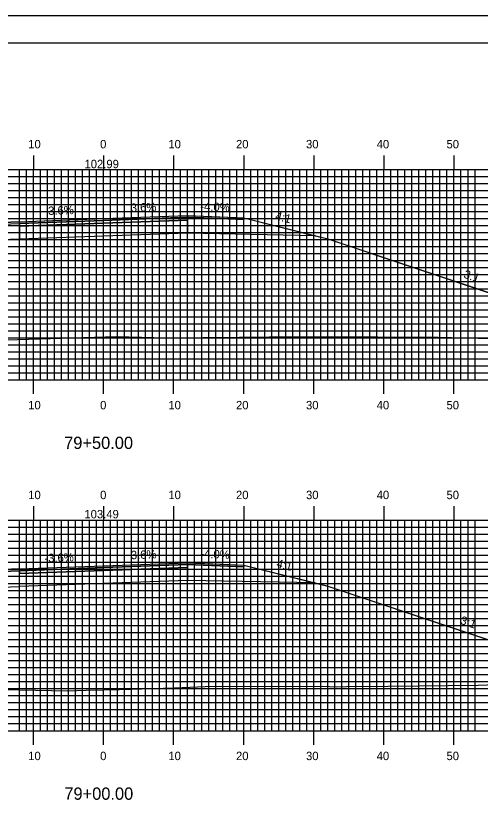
# Model space of a CAD drawing. Extents: x 1762184 to 1762528, y 442591 to 442811.
# Drawn here: x 1762337.8 to 1762404, y 442697.1 to 442810.5 of the extents above; entities that cross this region are included whole.
import ezdxf

# ---------------------------------------------------------------- set-up
doc = ezdxf.new("R2010")
doc.units = 0
for name, color, linetype in [('ANNOTATION', 7, 'Continuous'), ('BORDER', 7, 'Continuous'), ('D_Roadway_Centerline', 7, 'Continuous'), ('D_Roadway_Centerline_Text', 7, 'Continuous'), ('D_Roadway_Edge_Shoulder', 7, 'Continuous'), ('D_Roadway_Edge_TW', 7, 'Continuous'), ('D_Roadway_Pavement', 7, 'Continuous'), ('D_Roadway_SlopeLines', 7, 'Continuous'), ('D_Roadway_SubGrade', 7, 'Continuous'), ('H_V ANNOTATION', 7, 'Continuous'), ('MAJOR', 7, 'Continuous'), ('MINOR', 7, 'Continuous'), ('PLOT BOUNDARY', 7, 'Continuous'), ('S_Roadway_Centerline', 7, 'Continuous')]:
    doc.layers.add(name, color=color, linetype=linetype)

msp = doc.modelspace()

# ---------------------------------------------------------------- linework, layer by layer
at = {"layer": 'BORDER'}
msp.add_lwpolyline([(1762200.67, 442596.67), (1762520.67, 442596.67), (1762520.67, 442806.67), (1762200.67, 442806.67)], close=True, dxfattribs=at)
at = {"layer": 'D_Roadway_Centerline'}
for points in [[(1762326.92, 442780.77), (1762338.26, 442781.22), (1762338.27, 442781.22), (1762346.49, 442781.52), (1762350.26, 442781.66), (1762350.27, 442781.66), (1762350.27, 442781.66), (1762362.27, 442782.09), (1762362.27, 442782.09), (1762370.27, 442781.77), (1762380.13, 442779.3), (1762380.44, 442779.22), (1762380.51, 442779.21), (1762382.27, 442778.77), (1762382.28, 442778.76), (1762418.67, 442766.63)], [(1762332.89, 442731.51), (1762338.26, 442731.72), (1762338.27, 442731.72), (1762338.27, 442731.72), (1762346.33, 442732.01), (1762350.26, 442732.15), (1762350.27, 442732.16), (1762350.28, 442732.16), (1762362.27, 442732.59), (1762367.13, 442732.39), (1762370.27, 442732.27), (1762370.27, 442732.27), (1762380.44, 442729.72), (1762381.02, 442729.58), (1762382.27, 442729.27), (1762420.68, 442716.46)]]:
    msp.add_lwpolyline(points, dxfattribs=at)
at = {"layer": 'D_Roadway_Edge_Shoulder'}
for points in [[(1762362.27, 442782.09), (1762370.27, 442781.77), (1762370.27, 442781.52), (1762362.27, 442781.84)], [(1762338.27, 442781.22), (1762324.66, 442780.68), (1762324.66, 442780.43), (1762338.27, 442780.97)], [(1762362.27, 442732.59), (1762370.27, 442732.27), (1762370.27, 442732.02), (1762362.27, 442732.34)], [(1762338.27, 442731.72), (1762330.27, 442731.4), (1762330.27, 442731.4), (1762327.27, 442731.28), (1762327.27, 442731.03), (1762338.27, 442731.47)]]:
    msp.add_lwpolyline(points, close=True, dxfattribs=at)
at = {"layer": 'D_Roadway_Edge_TW'}
for points in [[(1762338.27, 442780.97), (1762338.27, 442781.22), (1762350.27, 442781.66), (1762362.27, 442782.09), (1762362.27, 442781.84), (1762350.27, 442781.41)], [(1762362.27, 442782.09), (1762362.27, 442782.09), (1762362.27, 442781.84), (1762362.27, 442781.84)], [(1762338.27, 442731.47), (1762338.27, 442731.72), (1762350.27, 442732.16), (1762362.27, 442732.59), (1762362.27, 442732.34), (1762350.27, 442731.91)]]:
    msp.add_lwpolyline(points, close=True, dxfattribs=at)
at = {"layer": 'D_Roadway_Pavement'}
for points in [[(1762338.27, 442780.56), (1762338.27, 442780.97), (1762350.27, 442781.41), (1762362.27, 442781.84), (1762362.27, 442781.42), (1762350.27, 442780.99)], [(1762362.27, 442781.84), (1762362.27, 442781.84), (1762362.27, 442781.42), (1762362.27, 442781.42)], [(1762338.27, 442731.06), (1762338.27, 442731.47), (1762350.27, 442731.91), (1762362.27, 442732.34), (1762362.27, 442731.92), (1762350.27, 442731.49)]]:
    msp.add_lwpolyline(points, close=True, dxfattribs=at)
for points in [[(1762362.27, 442781.84), (1762362.27, 442781.42)], [(1762362.27, 442781.84), (1762362.27, 442781.42)], [(1762362.27, 442781.84), (1762362.27, 442781.42)], [(1762338.27, 442731.47), (1762338.27, 442731.06)], [(1762362.27, 442732.34), (1762362.27, 442731.92)]]:
    msp.add_lwpolyline(points, dxfattribs=at)
at = {"layer": 'D_Roadway_SlopeLines'}
for points in [[(1762370.27, 442781.77), (1762382.27, 442778.77), (1762421.63, 442765.65)], [(1762370.27, 442732.27), (1762382.27, 442729.27), (1762421.95, 442716.04)]]:
    msp.add_lwpolyline(points, dxfattribs=at)
at = {"layer": 'D_Roadway_SubGrade'}
for points in [[(1762338.27, 442778.72), (1762338.27, 442780.56), (1762350.27, 442780.99), (1762362.27, 442781.42), (1762362.27, 442779.59), (1762350.27, 442779.16)], [(1762362.27, 442781.42), (1762362.27, 442781.84), (1762370.27, 442781.52), (1762370.27, 442781.77), (1762380.44, 442779.22), (1762362.27, 442779.59)], [(1762362.27, 442781.42), (1762362.27, 442781.42), (1762362.27, 442779.59), (1762362.27, 442779.59)], [(1762324.66, 442780.43), (1762338.27, 442780.97), (1762338.27, 442780.56), (1762338.27, 442778.72), (1762315.47, 442777.9), (1762324.66, 442780.68)], [(1762338.27, 442731.06), (1762338.27, 442731.47), (1762327.27, 442731.03), (1762327.27, 442731.28), (1762319.01, 442728.53), (1762338.27, 442729.22)], [(1762338.27, 442729.22), (1762338.27, 442731.47), (1762338.27, 442731.06), (1762350.27, 442731.49), (1762362.27, 442731.92), (1762362.27, 442732.34), (1762362.27, 442730.09), (1762350.27, 442729.66)], [(1762362.27, 442731.92), (1762362.27, 442732.34), (1762370.27, 442732.02), (1762370.27, 442732.27), (1762380.44, 442729.72), (1762362.27, 442730.09)]]:
    msp.add_lwpolyline(points, close=True, dxfattribs=at)
at = {"layer": 'MAJOR'}
for p, q in [((1762340.27, 442790.67), (1762340.27, 442788.67)), ((1762350.27, 442790.67), (1762350.27, 442788.67)), ((1762360.27, 442790.67), (1762360.27, 442788.67)), ((1762370.27, 442790.67), (1762370.27, 442788.67)), ((1762380.27, 442790.67), (1762380.27, 442788.67)), ((1762390.27, 442790.67), (1762390.27, 442788.67)), ((1762400.27, 442790.67), (1762400.27, 442788.67)), ((1762210.27, 442788.67), (1762490.27, 442788.67)), ((1762210.27, 442788.67), (1762490.27, 442788.67)), ((1762340.27, 442758.67), (1762340.27, 442788.67)), ((1762350.27, 442758.67), (1762350.27, 442788.67)), ((1762360.27, 442758.67), (1762360.27, 442788.67)), ((1762370.27, 442758.67), (1762370.27, 442788.67)), ((1762380.27, 442758.67), (1762380.27, 442788.67)), ((1762390.27, 442758.67), (1762390.27, 442788.67)), ((1762400.27, 442758.67), (1762400.27, 442788.67)), ((1762210.27, 442783.67), (1762490.27, 442783.67)), ((1762210.27, 442778.67), (1762490.27, 442778.67)), ((1762210.27, 442773.67), (1762490.27, 442773.67)), ((1762210.27, 442768.67), (1762490.27, 442768.67)), ((1762210.27, 442763.67), (1762490.27, 442763.67)), ((1762210.27, 442758.67), (1762490.27, 442758.67)), ((1762210.27, 442758.67), (1762490.27, 442758.67)), ((1762340.27, 442756.66), (1762340.27, 442758.67)), ((1762350.27, 442756.66), (1762350.27, 442758.67)), ((1762360.27, 442756.66), (1762360.27, 442758.67)), ((1762370.27, 442756.66), (1762370.27, 442758.67)), ((1762380.27, 442756.66), (1762380.27, 442758.67)), ((1762390.27, 442756.66), (1762390.27, 442758.67)), ((1762400.27, 442756.66), (1762400.27, 442758.67)), ((1762340.27, 442740.67), (1762340.27, 442738.67)), ((1762350.27, 442740.67), (1762350.27, 442738.67)), ((1762360.27, 442740.67), (1762360.27, 442738.67)), ((1762370.27, 442740.67), (1762370.27, 442738.67)), ((1762380.27, 442740.67), (1762380.27, 442738.67)), ((1762390.27, 442740.67), (1762390.27, 442738.67)), ((1762400.27, 442740.67), (1762400.27, 442738.67)), ((1762210.27, 442738.67), (1762490.27, 442738.67)), ((1762210.27, 442738.67), (1762490.27, 442738.67)), ((1762340.27, 442708.67), (1762340.27, 442738.67)), ((1762350.27, 442708.67), (1762350.27, 442738.67)), ((1762360.27, 442708.67), (1762360.27, 442738.67)), ((1762370.27, 442708.67), (1762370.27, 442738.67)), ((1762380.27, 442708.67), (1762380.27, 442738.67)), ((1762390.27, 442708.67), (1762390.27, 442738.67)), ((1762400.27, 442708.67), (1762400.27, 442738.67)), ((1762210.27, 442733.67), (1762490.27, 442733.67)), ((1762210.27, 442728.67), (1762490.27, 442728.67)), ((1762210.27, 442723.67), (1762490.27, 442723.67)), ((1762210.27, 442718.67), (1762490.27, 442718.67)), ((1762210.27, 442713.67), (1762490.27, 442713.67)), ((1762210.27, 442708.67), (1762490.27, 442708.67)), ((1762210.27, 442708.67), (1762490.27, 442708.67)), ((1762340.27, 442706.66), (1762340.27, 442708.67)), ((1762350.27, 442706.66), (1762350.27, 442708.67)), ((1762360.27, 442706.66), (1762360.27, 442708.67)), ((1762370.27, 442706.66), (1762370.27, 442708.67)), ((1762380.27, 442706.66), (1762380.27, 442708.67)), ((1762390.27, 442706.66), (1762390.27, 442708.67)), ((1762400.27, 442706.66), (1762400.27, 442708.67))]:
    msp.add_line(p, q, dxfattribs=at)
at = {"layer": 'MINOR'}
for p, q in [((1762338.27, 442758.67), (1762338.27, 442788.67)), ((1762339.27, 442758.67), (1762339.27, 442788.67)), ((1762341.27, 442758.67), (1762341.27, 442788.67)), ((1762342.27, 442758.67), (1762342.27, 442788.67)), ((1762343.27, 442758.67), (1762343.27, 442788.67)), ((1762344.27, 442758.67), (1762344.27, 442788.67)), ((1762345.27, 442758.67), (1762345.27, 442788.67)), ((1762346.27, 442758.67), (1762346.27, 442788.67)), ((1762347.27, 442758.67), (1762347.27, 442788.67)), ((1762348.27, 442758.67), (1762348.27, 442788.67)), ((1762349.27, 442758.67), (1762349.27, 442788.67)), ((1762351.27, 442758.67), (1762351.27, 442788.67)), ((1762352.27, 442758.67), (1762352.27, 442788.67)), ((1762353.27, 442758.67), (1762353.27, 442788.67)), ((1762354.27, 442758.67), (1762354.27, 442788.67)), ((1762355.27, 442758.67), (1762355.27, 442788.67)), ((1762356.27, 442758.67), (1762356.27, 442788.67)), ((1762357.27, 442758.67), (1762357.27, 442788.67)), ((1762358.27, 442758.67), (1762358.27, 442788.67)), ((1762359.27, 442758.67), (1762359.27, 442788.67)), ((1762361.27, 442758.67), (1762361.27, 442788.67)), ((1762362.27, 442758.67), (1762362.27, 442788.67)), ((1762363.27, 442758.67), (1762363.27, 442788.67)), ((1762364.27, 442758.67), (1762364.27, 442788.67)), ((1762365.27, 442758.67), (1762365.27, 442788.67)), ((1762366.27, 442758.67), (1762366.27, 442788.67)), ((1762367.27, 442758.67), (1762367.27, 442788.67)), ((1762368.27, 442758.67), (1762368.27, 442788.67)), ((1762369.27, 442758.67), (1762369.27, 442788.67)), ((1762371.27, 442758.67), (1762371.27, 442788.67)), ((1762372.27, 442758.67), (1762372.27, 442788.67)), ((1762373.27, 442758.67), (1762373.27, 442788.67)), ((1762374.27, 442758.67), (1762374.27, 442788.67)), ((1762375.27, 442758.67), (1762375.27, 442788.67)), ((1762376.27, 442758.67), (1762376.27, 442788.67)), ((1762377.27, 442758.67), (1762377.27, 442788.67)), ((1762378.27, 442758.67), (1762378.27, 442788.67)), ((1762379.27, 442758.67), (1762379.27, 442788.67)), ((1762381.27, 442758.67), (1762381.27, 442788.67)), ((1762382.27, 442758.67), (1762382.27, 442788.67)), ((1762383.27, 442758.67), (1762383.27, 442788.67)), ((1762384.27, 442758.67), (1762384.27, 442788.67)), ((1762385.27, 442758.67), (1762385.27, 442788.67)), ((1762386.27, 442758.67), (1762386.27, 442788.67)), ((1762387.27, 442758.67), (1762387.27, 442788.67)), ((1762388.27, 442758.67), (1762388.27, 442788.67)), ((1762389.27, 442758.67), (1762389.27, 442788.67)), ((1762391.27, 442758.67), (1762391.27, 442788.67)), ((1762392.27, 442758.67), (1762392.27, 442788.67)), ((1762393.27, 442758.67), (1762393.27, 442788.67)), ((1762394.27, 442758.67), (1762394.27, 442788.67)), ((1762395.27, 442758.67), (1762395.27, 442788.67)), ((1762396.27, 442758.67), (1762396.27, 442788.67)), ((1762397.27, 442758.67), (1762397.27, 442788.67)), ((1762398.27, 442758.67), (1762398.27, 442788.67)), ((1762399.27, 442758.67), (1762399.27, 442788.67)), ((1762401.27, 442758.67), (1762401.27, 442788.67)), ((1762402.27, 442758.67), (1762402.27, 442788.67)), ((1762403.27, 442758.67), (1762403.27, 442788.67)), ((1762210.27, 442787.67), (1762490.27, 442787.67)), ((1762210.27, 442786.67), (1762490.27, 442786.67)), ((1762210.27, 442785.67), (1762490.27, 442785.67)), ((1762210.27, 442784.67), (1762490.27, 442784.67)), ((1762210.27, 442782.67), (1762490.27, 442782.67)), ((1762210.27, 442781.67), (1762490.27, 442781.67)), ((1762210.27, 442780.67), (1762490.27, 442780.67)), ((1762210.27, 442779.67), (1762490.27, 442779.67)), ((1762210.27, 442777.67), (1762490.27, 442777.67)), ((1762210.27, 442776.67), (1762490.27, 442776.67)), ((1762210.27, 442775.67), (1762490.27, 442775.67)), ((1762210.27, 442774.67), (1762490.27, 442774.67)), ((1762210.27, 442772.67), (1762490.27, 442772.67)), ((1762210.27, 442771.67), (1762490.27, 442771.67)), ((1762210.27, 442770.67), (1762490.27, 442770.67)), ((1762210.27, 442769.67), (1762490.27, 442769.67)), ((1762210.27, 442767.67), (1762490.27, 442767.67)), ((1762210.27, 442766.67), (1762490.27, 442766.67)), ((1762210.27, 442765.67), (1762490.27, 442765.67)), ((1762210.27, 442764.67), (1762490.27, 442764.67)), ((1762210.27, 442762.67), (1762490.27, 442762.67)), ((1762210.27, 442761.67), (1762490.27, 442761.67)), ((1762210.27, 442760.67), (1762490.27, 442760.67)), ((1762210.27, 442759.67), (1762490.27, 442759.67)), ((1762338.27, 442708.67), (1762338.27, 442738.67)), ((1762339.27, 442708.67), (1762339.27, 442738.67)), ((1762341.27, 442708.67), (1762341.27, 442738.67)), ((1762342.27, 442708.67), (1762342.27, 442738.67)), ((1762343.27, 442708.67), (1762343.27, 442738.67)), ((1762344.27, 442708.67), (1762344.27, 442738.67)), ((1762345.27, 442708.67), (1762345.27, 442738.67)), ((1762346.27, 442708.67), (1762346.27, 442738.67)), ((1762347.27, 442708.67), (1762347.27, 442738.67)), ((1762348.27, 442708.67), (1762348.27, 442738.67)), ((1762349.27, 442708.67), (1762349.27, 442738.67)), ((1762351.27, 442708.67), (1762351.27, 442738.67)), ((1762352.27, 442708.67), (1762352.27, 442738.67)), ((1762353.27, 442708.67), (1762353.27, 442738.67)), ((1762354.27, 442708.67), (1762354.27, 442738.67)), ((1762355.27, 442708.67), (1762355.27, 442738.67)), ((1762356.27, 442708.67), (1762356.27, 442738.67)), ((1762357.27, 442708.67), (1762357.27, 442738.67)), ((1762358.27, 442708.67), (1762358.27, 442738.67)), ((1762359.27, 442708.67), (1762359.27, 442738.67)), ((1762361.27, 442708.67), (1762361.27, 442738.67)), ((1762362.27, 442708.67), (1762362.27, 442738.67)), ((1762363.27, 442708.67), (1762363.27, 442738.67)), ((1762364.27, 442708.67), (1762364.27, 442738.67)), ((1762365.27, 442708.67), (1762365.27, 442738.67)), ((1762366.27, 442708.67), (1762366.27, 442738.67)), ((1762367.27, 442708.67), (1762367.27, 442738.67)), ((1762368.27, 442708.67), (1762368.27, 442738.67)), ((1762369.27, 442708.67), (1762369.27, 442738.67)), ((1762371.27, 442708.67), (1762371.27, 442738.67)), ((1762372.27, 442708.67), (1762372.27, 442738.67)), ((1762373.27, 442708.67), (1762373.27, 442738.67)), ((1762374.27, 442708.67), (1762374.27, 442738.67)), ((1762375.27, 442708.67), (1762375.27, 442738.67)), ((1762376.27, 442708.67), (1762376.27, 442738.67)), ((1762377.27, 442708.67), (1762377.27, 442738.67)), ((1762378.27, 442708.67), (1762378.27, 442738.67)), ((1762379.27, 442708.67), (1762379.27, 442738.67)), ((1762381.27, 442708.67), (1762381.27, 442738.67)), ((1762382.27, 442708.67), (1762382.27, 442738.67)), ((1762383.27, 442708.67), (1762383.27, 442738.67)), ((1762384.27, 442708.67), (1762384.27, 442738.67)), ((1762385.27, 442708.67), (1762385.27, 442738.67)), ((1762386.27, 442708.67), (1762386.27, 442738.67)), ((1762387.27, 442708.67), (1762387.27, 442738.67)), ((1762388.27, 442708.67), (1762388.27, 442738.67)), ((1762389.27, 442708.67), (1762389.27, 442738.67)), ((1762391.27, 442708.67), (1762391.27, 442738.67)), ((1762392.27, 442708.67), (1762392.27, 442738.67)), ((1762393.27, 442708.67), (1762393.27, 442738.67)), ((1762394.27, 442708.67), (1762394.27, 442738.67)), ((1762395.27, 442708.67), (1762395.27, 442738.67)), ((1762396.27, 442708.67), (1762396.27, 442738.67)), ((1762397.27, 442708.67), (1762397.27, 442738.67)), ((1762398.27, 442708.67), (1762398.27, 442738.67)), ((1762399.27, 442708.67), (1762399.27, 442738.67)), ((1762401.27, 442708.67), (1762401.27, 442738.67)), ((1762402.27, 442708.67), (1762402.27, 442738.67)), ((1762403.27, 442708.67), (1762403.27, 442738.67)), ((1762210.27, 442737.67), (1762490.27, 442737.67)), ((1762210.27, 442736.67), (1762490.27, 442736.67)), ((1762210.27, 442735.67), (1762490.27, 442735.67)), ((1762210.27, 442734.67), (1762490.27, 442734.67)), ((1762210.27, 442732.67), (1762490.27, 442732.67)), ((1762210.27, 442731.67), (1762490.27, 442731.67)), ((1762210.27, 442730.67), (1762490.27, 442730.67)), ((1762210.27, 442729.67), (1762490.27, 442729.67)), ((1762210.27, 442727.67), (1762490.27, 442727.67)), ((1762210.27, 442726.67), (1762490.27, 442726.67)), ((1762210.27, 442725.67), (1762490.27, 442725.67)), ((1762210.27, 442724.67), (1762490.27, 442724.67)), ((1762210.27, 442722.67), (1762490.27, 442722.67)), ((1762210.27, 442721.67), (1762490.27, 442721.67)), ((1762210.27, 442720.67), (1762490.27, 442720.67)), ((1762210.27, 442719.67), (1762490.27, 442719.67)), ((1762210.27, 442717.67), (1762490.27, 442717.67)), ((1762210.27, 442716.67), (1762490.27, 442716.67)), ((1762210.27, 442715.67), (1762490.27, 442715.67)), ((1762210.27, 442714.67), (1762490.27, 442714.67)), ((1762210.27, 442712.67), (1762490.27, 442712.67)), ((1762210.27, 442711.67), (1762490.27, 442711.67)), ((1762210.27, 442710.67), (1762490.27, 442710.67)), ((1762210.27, 442709.67), (1762490.27, 442709.67))]:
    msp.add_line(p, q, dxfattribs=at)
at = {"layer": 'PLOT BOUNDARY'}
msp.add_lwpolyline([(1762184.48, 442590.55), (1762524.48, 442590.55), (1762524.48, 442810.55), (1762184.48, 442810.55)], close=True, dxfattribs=at)
at = {"layer": 'S_Roadway_Centerline'}
for points in [[(1762210.27, 442764.43), (1762228.23, 442764.73), (1762233.82, 442764.78), (1762239.74, 442764.65), (1762248.97, 442764.72), (1762253.17, 442764.72), (1762263.54, 442764.73), (1762272.55, 442764.79), (1762280.38, 442764.77), (1762287.62, 442764.62), (1762292.89, 442764.49), (1762309.79, 442764.84), (1762312.42, 442764.95), (1762318.72, 442764.73), (1762332.24, 442764.31), (1762334.82, 442764.33), (1762352.11, 442764.85), (1762359.24, 442764.67), (1762369.65, 442764.78), (1762371.28, 442764.74), (1762373.9, 442764.79), (1762389.4, 442764.82), (1762398, 442764.77), (1762405.61, 442764.58)], [(1762267.38, 442714.83), (1762277.69, 442714.96), (1762285.47, 442714.55), (1762289.59, 442714.53), (1762294.88, 442714.46), (1762300.94, 442714.53), (1762304.82, 442714.61), (1762323.81, 442714.78), (1762325.32, 442714.74), (1762329.07, 442714.69), (1762345.13, 442714.37), (1762347.81, 442714.46), (1762352.54, 442714.56), (1762360.38, 442714.79), (1762364.78, 442714.97), (1762381.51, 442715), (1762383.49, 442714.91), (1762384.95, 442714.97), (1762390.9, 442714.99), (1762403.74, 442715.17), (1762411.4, 442715.43)]]:
    msp.add_lwpolyline(points, dxfattribs=at)

# ---------------------------------------------------------------- texts
at = {"layer": 'ANNOTATION'}
for s, rotation, p in [('3.6%', 2.0618, (1762354.17, 442782.6)), ('-4.0%', 357.7094, (1762364.06, 442782.82)), ('-3.6%', 2.0617, (1762341.85, 442782.15)), ('4:1', 345.9607, (1762374.7, 442781.52)), ('3:1', 341.5644, (1762401.56, 442773.25)), ('-3.6%', 2.0617, (1762341.85, 442732.65)), ('3.6%', 2.0618, (1762354.18, 442733.1)), ('-4.0%', 357.7093, (1762364.06, 442733.32)), ('4:1', 345.962, (1762374.86, 442731.98)), ('3:1', 341.5642, (1762401.08, 442723.91))]:
    msp.add_text(s, height=1.2, rotation=rotation, dxfattribs=at).set_placement(p)
at = {"layer": 'D_Roadway_Centerline'}
for s, p in [('C', (1762350.26, 442781.66)), ('L', (1762350.27, 442781.65)), ('C', (1762350.26, 442732.16)), ('L', (1762350.27, 442732.15))]:
    msp.add_text(s, height=0.0146, dxfattribs=at).set_placement(p)
at = {"layer": 'D_Roadway_Centerline_Text'}
for s, p in [('102.99', (1762347.55, 442788.84)), ('103.49', (1762347.54, 442738.93))]:
    msp.add_text(s, height=1.2, dxfattribs=at).set_placement(p)
at = {"layer": 'H_V ANNOTATION'}
for s, height, p in [('10', 1.2, (1762339.52, 442791.67)), ('0', 1.2, (1762349.78, 442791.67)), ('10', 1.2, (1762359.52, 442791.67)), ('20', 1.2, (1762369.17, 442791.67)), ('30', 1.2, (1762379.16, 442791.67)), ('40', 1.2, (1762389.24, 442791.67)), ('50', 1.2, (1762399.2, 442791.67)), ('10', 1.2, (1762339.52, 442754.47)), ('0', 1.2, (1762349.78, 442754.47)), ('10', 1.2, (1762359.52, 442754.47)), ('20', 1.2, (1762369.17, 442754.47)), ('30', 1.2, (1762379.16, 442754.47)), ('40', 1.2, (1762389.24, 442754.47)), ('50', 1.2, (1762399.2, 442754.47)), ('79+50.00', 1.75, (1762344.65, 442748.82)), ('10', 1.2, (1762339.52, 442741.67)), ('0', 1.2, (1762349.78, 442741.67)), ('10', 1.2, (1762359.52, 442741.67)), ('20', 1.2, (1762369.17, 442741.67)), ('30', 1.2, (1762379.16, 442741.67)), ('40', 1.2, (1762389.24, 442741.67)), ('50', 1.2, (1762399.2, 442741.67)), ('10', 1.2, (1762339.52, 442704.47)), ('0', 1.2, (1762349.78, 442704.47)), ('10', 1.2, (1762359.52, 442704.47)), ('20', 1.2, (1762369.17, 442704.47)), ('30', 1.2, (1762379.16, 442704.47)), ('40', 1.2, (1762389.24, 442704.47)), ('50', 1.2, (1762399.2, 442704.47)), ('79+00.00', 1.75, (1762344.68, 442698.82))]:
    msp.add_text(s, height=height, dxfattribs=at).set_placement(p)

doc.saveas('drawing.dxf')
